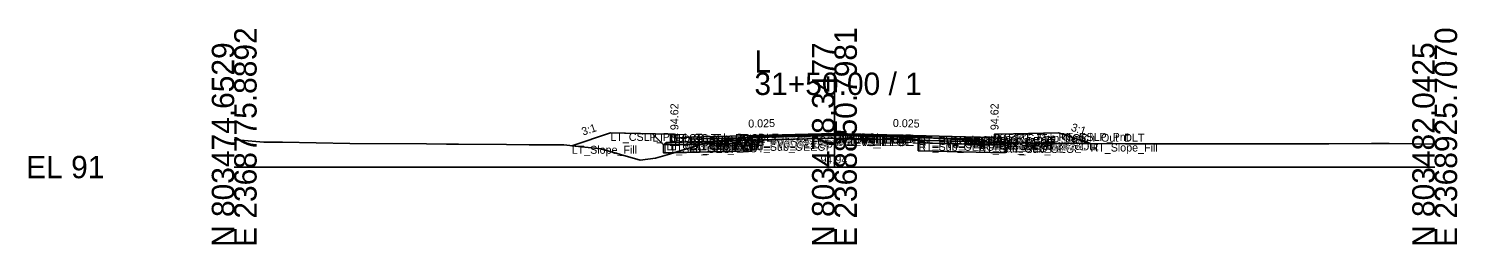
# Model space of a CAD drawing. Extents: x -26 to 8153, y -10 to 9520.
# Drawn here: x 1974.3 to 2152.8, y 4990.3 to 5017.3 of the extents above; entities that cross this region are included whole.
import ezdxf

# ---------------------------------------------------------------- set-up
doc = ezdxf.new("R2010")
doc.units = 0
for name, color, linetype in [('Exist CMT Pavement', 7, 'Continuous'), ('Exist Cross Section Cell', 7, 'Continuous'), ('Exist XS Center Line Elevation Label', 7, 'Continuous'), ('Exist XS Ground Line', 7, 'Continuous'), ('Prop CMT Conc Surface', 7, 'Continuous'), ('Prop CMT Concrete Structures', 7, 'Continuous'), ('Prop CMT Pvmt Course 1', 7, 'Continuous'), ('Prop CMT Pvmt Course 1 CG', 7, 'Continuous'), ('Prop CMT Pvmt Course 1 Wedge', 7, 'Continuous'), ('Prop CMT Pvmt Course 2', 7, 'Continuous'), ('Prop CMT Pvmt Course 2 Wedge', 7, 'Continuous'), ('Prop CMT Pvmt Course 3', 7, 'Continuous'), ('Prop CMT Pvmt Course 3 Wedge', 7, 'Continuous'), ('Prop CMT Pvmt Surface', 7, 'Continuous'), ('Prop CMT Pvmt Wedge Surface 1', 7, 'Continuous'), ('Prop CMT Pvmt Wedge Surface 2', 7, 'Continuous'), ('Prop CMT Pvmt Wedge Surface 3', 7, 'Continuous'), ('Prop CMT Shallow Undercut', 7, 'Continuous'), ('Prop CMT Shallow Undercut Boundary', 7, 'Continuous'), ('Prop CMT Slope Grass', 7, 'Continuous'), ('Prop CMT Subgrade Earthwork', 7, 'Continuous'), ('Prop XS Earthwork Shape', 7, 'Continuous'), ('Prop XS Hydro Elevations', 7, 'Continuous'), ('Prop XS SE Text', 7, 'Continuous'), ('Prop XS Side Slope Text', 7, 'Continuous'), ('Prop XS Subgrade Earthwork', 7, 'Continuous'), ('Scratch_Level_2', 7, 'Continuous'), ('Scratch_Level_6', 7, 'Continuous')]:
    doc.layers.add(name, color=color, linetype=linetype)

msp = doc.modelspace()

# ---------------------------------------------------------------- linework, layer by layer
at = {"layer": 'Exist CMT Pavement'}
for p, q in [((2064.62, 5003.69), (2071.58, 5003.86)), ((2071.58, 5003.86), (2074.76, 5003.94)), ((2074.76, 5003.94), (2078.04, 5003.91)), ((2078.04, 5003.91), (2085.48, 5003.86))]:
    msp.add_line(p, q, dxfattribs=at)
at = {"layer": 'Exist Cross Section Cell'}
for p, q in [((2075, 5000), (2075, 5011.82)), ((2000, 5000), (2075, 5000)), ((2075, 5000), (2150, 5000))]:
    msp.add_line(p, q, dxfattribs=at)
at = {"layer": 'Exist XS Ground Line'}
for p, q in [((2000, 5003.39), (2000.75, 5003.36)), ((2000.75, 5003.36), (2003.72, 5003.11)), ((2003.72, 5003.11), (2006.03, 5003.13)), ((2006.03, 5003.13), (2014.43, 5002.93)), ((2014.43, 5002.93), (2024.02, 5002.92)), ((2024.02, 5002.92), (2026.53, 5002.87)), ((2026.53, 5002.87), (2027.32, 5002.86)), ((2027.32, 5002.86), (2028.04, 5002.88)), ((2028.04, 5002.88), (2034.04, 5002.84)), ((2034.04, 5002.84), (2036.87, 5002.8)), ((2036.87, 5002.8), (2041.18, 5002.77)), ((2041.18, 5002.77), (2043.83, 5002.48)), ((2054.38, 5001.63), (2058.94, 5003.02)), ((2058.94, 5003.02), (2061.01, 5003.37)), ((2061.01, 5003.37), (2064.62, 5003.69)), ((2064.62, 5003.69), (2071.58, 5003.86)), ((2071.58, 5003.86), (2074.76, 5003.94)), ((2074.76, 5003.94), (2078.04, 5003.91)), ((2078.04, 5003.91), (2085.48, 5003.86)), ((2085.48, 5003.86), (2085.9, 5003.72)), ((2085.9, 5003.72), (2086.8, 5003.65)), ((2086.8, 5003.65), (2087.95, 5003.57)), ((2087.95, 5003.57), (2091.32, 5003.41)), ((2091.32, 5003.41), (2091.96, 5003.35)), ((2091.96, 5003.35), (2094.14, 5003.13)), ((2094.14, 5003.13), (2094.98, 5003.11)), ((2094.98, 5003.11), (2097.48, 5003.05)), ((2097.48, 5003.05), (2099.77, 5002.99)), ((2099.77, 5002.99), (2111.36, 5002.91)), ((2111.36, 5002.91), (2116.47, 5002.89)), ((2116.47, 5002.89), (2128.99, 5002.89)), ((2128.99, 5002.89), (2136.76, 5002.89)), ((2136.76, 5002.89), (2142.11, 5002.93)), ((2142.11, 5002.93), (2144.32, 5002.95)), ((2144.32, 5002.95), (2150, 5002.86)), ((2043.83, 5002.48), (2045.8, 5002.29)), ((2045.8, 5002.29), (2050.72, 5000.86)), ((2050.72, 5000.86), (2052.62, 5001.12)), ((2052.62, 5001.12), (2054.38, 5001.63))]:
    msp.add_line(p, q, dxfattribs=at)
at = {"layer": 'Prop CMT Conc Surface'}
for points in [[(2055, 5003.62), (2055, 5004.12), (2054.5, 5004.12)], [(2057, 5003.75), (2055, 5003.62)], [(2093, 5003.75), (2095, 5003.62)], [(2095, 5003.62), (2095, 5004.12), (2095.5, 5004.12)]]:
    msp.add_lwpolyline(points, dxfattribs=at)
at = {"layer": 'Prop CMT Concrete Structures'}
for points in [[(2057, 5003.75), (2055, 5003.62), (2055, 5004.12), (2054.5, 5004.12)], [(2054.5, 5004.12), (2054.5, 5003.11), (2057, 5003.17)], [(2057, 5003.17), (2057, 5003.75)], [(2093, 5003.75), (2095, 5003.62), (2095, 5004.12), (2095.5, 5004.12)], [(2095.5, 5004.12), (2095.5, 5003.11), (2093, 5003.17)], [(2093, 5003.17), (2093, 5003.75)]]:
    msp.add_lwpolyline(points, dxfattribs=at)
at = {"layer": 'Prop CMT Pvmt Course 1'}
for points in [[(2075, 5004.2), (2057, 5003.75)], [(2057, 5003.75), (2057, 5003.5)], [(2057, 5003.5), (2064.62, 5003.69)], [(2064.62, 5003.82), (2075, 5004.08)], [(2064.62, 5003.69), (2064.62, 5003.82)], [(2075, 5003.95), (2075, 5004.2)], [(2075, 5004.2), (2093, 5003.75)], [(2075, 5003.95), (2075, 5004.2)], [(2075, 5004.08), (2075, 5003.95), (2075, 5003.95)], [(2085.48, 5003.82), (2075, 5004.08)], [(2075, 5004.08), (2075, 5003.95), (2075, 5003.95)], [(2085.48, 5003.69), (2085.48, 5003.82)], [(2093, 5003.5), (2085.48, 5003.69)], [(2093, 5003.75), (2093, 5003.5)]]:
    msp.add_lwpolyline(points, dxfattribs=at)
at = {"layer": 'Prop CMT Pvmt Course 1 CG'}
for points in [[(2057, 5003.17), (2054, 5003.09), (2053.66, 5002.76)], [(2053.66, 5002.76), (2057, 5002.84)], [(2057, 5002.84), (2057, 5003.17)], [(2093, 5003.17), (2096, 5003.09), (2096.34, 5002.76)], [(2093, 5002.84), (2093, 5003.17)], [(2096.34, 5002.76), (2093, 5002.84)]]:
    msp.add_lwpolyline(points, dxfattribs=at)
at = {"layer": 'Prop CMT Pvmt Course 1 Wedge'}
for points in [[(2075, 5004.08), (2064.62, 5003.82)], [(2075, 5004.08), (2085.48, 5003.82)]]:
    msp.add_lwpolyline(points, dxfattribs=at)
at = {"layer": 'Prop CMT Pvmt Course 2'}
for points in [[(2064.62, 5003.69), (2057, 5003.5)], [(2057, 5003.5), (2057, 5003.17)], [(2057, 5003.17), (2064.62, 5003.36)], [(2064.62, 5003.36), (2064.62, 5003.69)], [(2085.48, 5003.36), (2085.48, 5003.69)], [(2085.48, 5003.69), (2093, 5003.5)], [(2093, 5003.17), (2085.48, 5003.36)], [(2093, 5003.5), (2093, 5003.17)]]:
    msp.add_lwpolyline(points, dxfattribs=at)
at = {"layer": 'Prop CMT Pvmt Course 2 Wedge'}
for points in [[(2075, 5003.95), (2064.62, 5003.69)], [(2075, 5003.95), (2085.48, 5003.69)]]:
    msp.add_lwpolyline(points, dxfattribs=at)
at = {"layer": 'Prop CMT Pvmt Course 3'}
for points in [[(2064.62, 5003.36), (2057, 5003.17)], [(2057, 5003.17), (2057, 5002.84)], [(2057, 5002.84), (2064.62, 5003.03)], [(2064.62, 5003.03), (2064.62, 5003.36)], [(2085.48, 5003.36), (2093, 5003.17)], [(2085.48, 5003.03), (2085.48, 5003.36)], [(2093, 5002.84), (2085.48, 5003.03)], [(2093, 5003.17), (2093, 5002.84)]]:
    msp.add_lwpolyline(points, dxfattribs=at)
at = {"layer": 'Prop CMT Pvmt Course 3 Wedge'}
for points in [[(2075, 5003.62), (2064.62, 5003.36)], [(2075, 5003.62), (2085.48, 5003.36)]]:
    msp.add_lwpolyline(points, dxfattribs=at)
at = {"layer": 'Prop CMT Pvmt Surface'}
for points in [[(2075, 5004.2), (2057, 5003.75)], [(2075, 5004.2), (2093, 5003.75)]]:
    msp.add_lwpolyline(points, dxfattribs=at)
at = {"layer": 'Prop CMT Pvmt Wedge Surface 1'}
for points in [[(2057, 5003.5), (2057, 5003.75)], [(2064.62, 5003.69), (2057, 5003.5)], [(2075, 5004.08), (2064.62, 5003.82)], [(2064.62, 5003.82), (2064.62, 5003.69)], [(2075, 5004.08), (2085.48, 5003.82)], [(2085.48, 5003.82), (2085.48, 5003.69)], [(2085.48, 5003.69), (2093, 5003.5)], [(2093, 5003.5), (2093, 5003.75)]]:
    msp.add_lwpolyline(points, dxfattribs=at)
at = {"layer": 'Prop CMT Pvmt Wedge Surface 2'}
for points in [[(2075, 5003.95), (2057, 5003.5)], [(2057, 5003.5), (2057, 5003.75)], [(2075, 5003.95), (2093, 5003.5)], [(2093, 5003.5), (2093, 5003.75)]]:
    msp.add_lwpolyline(points, dxfattribs=at)
at = {"layer": 'Prop CMT Pvmt Wedge Surface 3'}
for points in [[(2057, 5003.17), (2057, 5003.75)], [(2075, 5003.62), (2057, 5003.17)], [(2075, 5003.62), (2093, 5003.17)], [(2093, 5003.17), (2093, 5003.75)]]:
    msp.add_lwpolyline(points, dxfattribs=at)
at = {"layer": 'Prop CMT Shallow Undercut'}
for p, q in [((2096.34, 5002.76), (2085.48, 5003.03)), ((2085.48, 5003.03), (2085.48, 5002.03)), ((2096.34, 5001.76), (2096.34, 5002.76)), ((2085.48, 5002.03), (2096.34, 5001.76))]:
    msp.add_line(p, q, dxfattribs=at)
msp.add_lwpolyline([(2054.91, 5001.79), (2058.47, 5002.88), (2064.62, 5003.03), (2064.62, 5002.03)], close=True, dxfattribs=at)
at = {"layer": 'Prop CMT Shallow Undercut Boundary'}
for p, q in [((2053.66, 5002.76), (2064.62, 5003.03)), ((2053.66, 5002.76), (2053.66, 5001.76)), ((2064.62, 5003.03), (2064.62, 5002.03)), ((2085.48, 5003.03), (2085.48, 5002.03)), ((2085.48, 5003.03), (2096.34, 5002.76)), ((2096.34, 5002.76), (2096.34, 5001.76)), ((2053.66, 5001.76), (2064.62, 5002.03)), ((2096.34, 5001.76), (2085.48, 5002.03))]:
    msp.add_line(p, q, dxfattribs=at)
at = {"layer": 'Prop CMT Slope Grass'}
for points in [[(2054.5, 5004.12), (2047, 5004.27), (2042.17, 5002.66)], [(2095.5, 5004.12), (2103, 5004.27), (2106.99, 5002.94)]]:
    msp.add_lwpolyline(points, dxfattribs=at)
at = {"layer": 'Prop CMT Subgrade Earthwork'}
for points in [[(2057, 5002.84), (2053.66, 5002.76), (2052.25, 5004.17)], [(2064.62, 5003.03), (2057, 5002.84)], [(2064.62, 5003.03), (2064.63, 5003.69)], [(2085.48, 5003.03), (2085.46, 5003.86)], [(2085.48, 5003.03), (2093, 5002.84)], [(2093, 5002.84), (2096.34, 5002.76), (2097.75, 5004.17)]]:
    msp.add_lwpolyline(points, dxfattribs=at)
at = {"layer": 'Prop XS Earthwork Shape'}
for points in [[(2047, 5004.27), (2042.17, 5002.66), (2043.83, 5002.48), (2045.8, 5002.29), (2050.72, 5000.86), (2052.62, 5001.12), (2054.38, 5001.63), (2054.91, 5001.79), (2053.66, 5001.76), (2053.66, 5002.76), (2052.25, 5004.17)], [(2096.65, 5003.07), (2097.75, 5004.17), (2103, 5004.27), (2106.99, 5002.94), (2099.77, 5002.99), (2097.48, 5003.05)], [(2058.47, 5002.88), (2057, 5002.84), (2053.66, 5002.76), (2053.66, 5001.76), (2054.91, 5001.79)], [(2054.91, 5001.79), (2064.62, 5002.03), (2064.62, 5003.03), (2058.47, 5002.88)], [(2058.47, 5002.88), (2058.94, 5003.02), (2061.01, 5003.37), (2064.62, 5003.69), (2064.63, 5003.69), (2064.62, 5003.03)], [(2094.98, 5003.11), (2096.65, 5003.07), (2096.34, 5002.76), (2093, 5002.84), (2085.48, 5003.03), (2085.46, 5003.86), (2085.48, 5003.86), (2085.9, 5003.72), (2086.8, 5003.65), (2087.95, 5003.57), (2091.32, 5003.41), (2091.96, 5003.35), (2094.14, 5003.13)], [(2096.34, 5001.76), (2085.48, 5002.03), (2085.48, 5003.03), (2093, 5002.84), (2096.34, 5002.76)]]:
    msp.add_lwpolyline(points, close=True, dxfattribs=at)
at = {"layer": 'Prop XS Subgrade Earthwork'}
for p, q in [((2053.66, 5002.76), (2064.62, 5003.03)), ((2085.48, 5003.03), (2096.34, 5002.76))]:
    msp.add_line(p, q, dxfattribs=at)
at = {"layer": 'Scratch_Level_6'}
for p, q in [((2096.34, 5002.76), (2085.48, 5003.03)), ((2085.48, 5003.03), (2085.48, 5002.03)), ((2096.34, 5001.76), (2096.34, 5002.76)), ((2085.48, 5002.03), (2096.34, 5001.76))]:
    msp.add_line(p, q, dxfattribs=at)
msp.add_lwpolyline([(2054.91, 5001.79), (2058.47, 5002.88), (2064.62, 5003.03), (2064.62, 5002.03)], close=True, dxfattribs=at)

# ---------------------------------------------------------------- texts
at = {"layer": 'Exist Cross Section Cell'}
for s, p in [('E 2368775.8892', (2002.8, 4990)), ('E 2368850.7981', (2077.8, 4990)), ('E 2368925.7070', (2152.8, 4990)), ('N 803474.6529', (2000, 4990)), ('N 803478.3477', (2075, 4990)), ('N 803482.0425', (2150, 4990))]:
    msp.add_text(s, height=2.8, rotation=90, dxfattribs=at).set_placement(p)
for s, p in [('L', (2065, 5011.82)), ('31+50.00 / 1', (2065, 5009.02)), ('EL 91', (1974, 4998.6))]:
    msp.add_text(s, height=2.8, dxfattribs=at).set_placement(p)
at = {"layer": 'Exist XS Center Line Elevation Label'}
msp.add_text('94.94', height=1, dxfattribs=at).set_placement((2073.26, 5000.44))
at = {"layer": 'Prop XS Hydro Elevations'}
for p in [(2055.5, 5004.62), (2095.5, 5004.62)]:
    msp.add_text('94.62', height=1, rotation=90, dxfattribs=at).set_placement(p)
at = {"layer": 'Prop XS SE Text'}
for rotation, p in [(1.4321, (2064.24, 5004.93)), (358.5679, (2082.29, 5005.02))]:
    msp.add_text('0.025', height=1, rotation=rotation, dxfattribs=at).set_placement(p)
at = {"layer": 'Prop XS Side Slope Text'}
for rotation, p in [(18.4349, (2043.59, 5003.93)), (341.5651, (2104.48, 5004.57))]:
    msp.add_text('3:1', height=1, rotation=rotation, dxfattribs=at).set_placement(p)
at = {"layer": 'Scratch_Level_2'}
for s, p in [('LT_CSLP_Pnt', (2047, 5003.27)), ('RT_CSLP_Pnt', (2103, 5003.27)), ('LT_Slope_Fill', (2042.17, 5001.66)), ('LT_Sub_Trench_Out_DLT', (2052.25, 5003.17)), ('LT_Sub_OEOP', (2053.66, 5001.76)), ('LT_CG1_Shelf_Out', (2054, 5002.09)), ('LT_CG_Top_BOC', (2054.5, 5003.12)), ('LT_CG_Bot_BOC', (2054.5, 5002.11)), ('LT_CG_Top_Face', (2055, 5003.12)), ('LT_CG_Top_Gut', (2055, 5002.62)), ('LT_PV1_OEOT', (2057, 5002.75)), ('LT_PV2_OEOT', (2057, 5002.5)), ('LT_PV3_OEOT', (2057, 5002.17)), ('LT_CG_Bot_IE', (2057, 5002.17)), ('LT_Sub_OEOT', (2057, 5001.84)), ('LT_PV1_OEEOP', (2064.62, 5002.82)), ('LT_PV_OEEOP_EG', (2064.62, 5002.69)), ('LT_PV2_OEEOP', (2064.62, 5002.69)), ('LT_PV3_OEEOP', (2064.62, 5002.36)), ('LT_Sub_OEEOP', (2064.62, 5002.03)), ('LT_PV_Sub_Tie_Out', (2064.63, 5002.69)), ('PV1_PGL', (2075, 5003.2)), ('RT_PV1_IEEOP', (2075, 5003.08)), ('LT_PV1_IEEOP', (2075, 5003.08)), ('RT_PV2_IEEOP', (2075, 5002.95)), ('LT_PV2_IEEOP', (2075, 5002.95)), ('PV2_PGL', (2075, 5002.95)), ('RT_PV_IEEOP_EG', (2075, 5002.94)), ('LT_PV_IEEOP_EG', (2075, 5002.94)), ('RT_PV3_IEEOP', (2075, 5002.62)), ('LT_PV3_IEEOP', (2075, 5002.62)), ('RT_PV_Sub_Tie_Out', (2085.46, 5002.86)), ('RT_PV_OEEOP_EG', (2085.48, 5002.86)), ('RT_PV1_OEEOP', (2085.48, 5002.82)), ('RT_PV2_OEEOP', (2085.48, 5002.69)), ('RT_PV3_OEEOP', (2085.48, 5002.36)), ('RT_Sub_OEEOP', (2085.48, 5002.03)), ('RT_PV1_OEOT', (2093, 5002.75)), ('RT_PV2_OEOT', (2093, 5002.5)), ('RT_PV3_OEOT', (2093, 5002.17)), ('RT_CG_Bot_IE', (2093, 5002.17)), ('RT_Sub_OEOT', (2093, 5001.84)), ('RT_CG_Top_Face', (2095, 5003.12)), ('RT_CG_Top_Gut', (2095, 5002.62)), ('RT_CG_Top_BOC', (2095.5, 5003.12)), ('RT_CG_Bot_BOC', (2095.5, 5002.11)), ('RT_CG1_Shelf_Out', (2096, 5002.09)), ('RT_Sub_OEOP', (2096.34, 5001.76)), ('RT_Sub_Trench_Out_DLT', (2097.75, 5003.17)), ('RT_Slope_Fill', (2106.99, 5001.94))]:
    msp.add_text(s, height=1, dxfattribs=at).set_placement(p)

doc.saveas('drawing.dxf')
